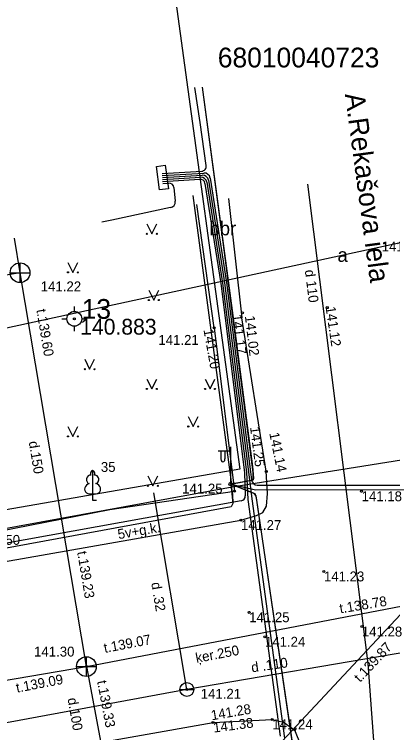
# Model space of a CAD drawing. Extents: x 728492 to 729038, y 272968 to 273171.
# Drawn here: x 728801.6 to 728820.75, y 273094.51 to 273130.85 of the extents above; entities that cross this region are included whole.
import ezdxf

# ---------------------------------------------------------------- set-up
doc = ezdxf.new("R2010")
doc.units = 0
for name, color, linetype in [('APGR_SARK_####_####_#', 7, 'Continuous'), ('APGS_ACRL_####_####_#', 7, 'Continuous'), ('APGS_ELEM_####_####_#', 7, 'Continuous'), ('APGS_VADP_ZSPR_####_I', 7, 'Continuous'), ('CELI_CAPM_####_####_#', 7, 'Continuous'), ('CELI_CMAL_####_####_#', 7, 'Continuous'), ('CELI_CSEG_####_TKST_#', 7, 'Continuous'), ('CELI_IELA_####_TKST_#', 7, 'Continuous'), ('ELEK_ELEM_####_####_#', 7, 'Continuous'), ('ELEK_VADP_ZSPR_####_I', 7, 'Continuous'), ('ELEK_VADV_ZSPR_TKST_#', 7, 'Continuous'), ('GEOD_ELEM_####_####_#', 7, 'Continuous'), ('GEOD_ELEM_####_TKST_#', 7, 'Continuous'), ('RAMI_UZMR_####_####_#', 7, 'Continuous'), ('RELJ_AATZ_####_TKST_#', 7, 'Continuous'), ('RELJ_ELEM_####_####_#', 7, 'Continuous'), ('ROBZ_KADS_####_TKST_#', 7, 'Continuous'), ('ROBZ_UZMR_####_####_#', 7, 'Continuous'), ('SKAN_ELEM_####_####_#', 7, 'Continuous'), ('SKAN_ELEM_PAST_TKST_#', 7, 'Continuous'), ('SKAN_VADP_PAST_####_#', 7, 'Continuous'), ('SKAN_VADP_PAST_TKST_#', 7, 'Continuous'), ('TERT_DIAM_####_TKST_#', 7, 'Continuous'), ('TERT_ELEM_####_####_#', 7, 'Continuous'), ('UDTK_ELEM_####_####_#', 7, 'Continuous'), ('UDTK_ELEM_####_TKST_#', 7, 'Continuous'), ('UDTK_VADP_UDEN_####_#', 7, 'Continuous'), ('UDTK_VADP_UDEN_TKST_#', 7, 'Continuous')]:
    doc.layers.add(name, color=color, linetype=linetype)

msp = doc.modelspace()

# ---------------------------------------------------------------- linework, layer by layer
at = {"layer": 'APGR_SARK_####_####_#'}
for points in [[(728809.481, 273133.58), (728813.011, 273107.831)], [(728813.011, 273107.831), (728678.847, 273084.513)]]:
    msp.add_lwpolyline(points, dxfattribs=at)
at = {"layer": 'APGS_ACRL_####_####_#'}
for points in [[(728812.551, 273107.084), (728813.681, 273107.292), (728813.683, 273107.676), (728812.175, 273119.32), (728811.115, 273127.168)], [(728812.551, 273107.084), (728813.808, 273106.798), (728827.684, 273106.812), (728831.005, 273108.951), (728844.549, 273111.459)], [(728812.551, 273107.084), (728812.657, 273106.097), (728812.582, 273105.93), (728789.256, 273101.647)], [(728819.245, 273070.039), (728816.435, 273088.774), (728813.852, 273106.392), (728813.783, 273106.59), (728812.551, 273107.084)]]:
    msp.add_lwpolyline(points, dxfattribs=at)
at = {"layer": 'APGS_ELEM_####_####_#'}
for p, q in [((728812.551, 273108.751), (728811.916, 273108.746)), ((728812.051, 273108.747), (728812.051, 273108.355)), ((728812.261, 273108.749), (728812.261, 273108.355)), ((728812.551, 273107.084), (728812.551, 273108.967))]:
    msp.add_line(p, q, dxfattribs=at)
msp.add_circle((728812.551, 273107.084), 0.09, dxfattribs=at)
msp.add_ellipse((728812.156, 273108.355), major_axis=(0, 0.151), ratio=0.695971, start_param=1.570796, end_param=4.712389, dxfattribs=at)
at = {"layer": 'APGS_VADP_ZSPR_####_I'}
for points in [[(728811.109, 273127.168), (728812.666, 273115.604), (728813.66, 273107.967), (728813.707, 273107.385), (728813.681, 273107.292), (728813.602, 273107.257), (728812.551, 273107.084)], [(728812.551, 273107.084), (728813.18, 273106.941), (728813.808, 273106.798), (728827.684, 273106.812), (728831.005, 273108.951), (728843.77, 273111.313)], [(728812.551, 273107.084), (728812.644, 273106.556), (728812.657, 273106.097), (728812.582, 273105.93), (728789.256, 273101.647)], [(728812.551, 273107.084), (728813.167, 273106.837), (728813.712, 273106.629), (728813.818, 273106.491), (728816.417, 273088.868), (728819.242, 273070.038)]]:
    msp.add_lwpolyline(points, dxfattribs=at)
at = {"layer": 'CELI_CAPM_####_####_#'}
msp.add_line((728814.353, 273107.731), (728813.116, 273115.489), dxfattribs=at)
for points in [[(728812.431, 273121.524), (728813.116, 273115.489)], [(728778, 273098.805), (728793.44, 273101.816), (728813.067, 273105.258), (728813.855, 273105.497), (728814.183, 273105.647), (728814.358, 273105.969), (728814.419, 273106.601), (728814.353, 273107.731)], [(728676.374, 273071.049), (728680.397, 273071.606), (728696.384, 273074.602), (728721.076, 273079.042), (728739.743, 273082.405), (728759.114, 273085.751), (728811.654, 273095.023), (728814.654, 273095.178), (728815.22, 273095.032), (728815.785, 273094.657), (728816.384, 273093.154), (728816.384, 273093.154), (728817.477, 273084.163), (728819.159, 273072.476)]]:
    msp.add_lwpolyline(points, dxfattribs=at)
at = {"layer": 'CELI_CMAL_####_####_#'}
for p, q in [((728811.715, 273114.983), (728810.832, 273121.229)), ((728811.715, 273114.983), (728812.742, 273106.717)), ((728806.433, 273105.789), (728812.742, 273106.717)), ((728799.84, 273104.509), (728806.433, 273105.789))]:
    msp.add_line(p, q, dxfattribs=at)
at = {"layer": 'ELEK_ELEM_####_####_#'}
msp.add_lwpolyline([(728809.235, 273123.213), (728809.395, 273122.023), (728808.949, 273121.963), (728808.789, 273123.153)], close=True, dxfattribs=at)
at = {"layer": 'ELEK_VADP_ZSPR_####_I'}
for p, q in [((728809.08, 273122.788), (728811.081, 273122.912)), ((728809.086, 273122.688), (728811.193, 273122.819)), ((728809.098, 273122.488), (728811.024, 273122.608)), ((728809.104, 273122.388), (728810.985, 273122.505)), ((728809.111, 273122.289), (728809.412, 273122.307)), ((728813.896, 273107.029), (728827.6, 273107.031))]:
    msp.add_line(p, q, dxfattribs=at)
for points in [[(728811.313, 273123.197), (728810.998, 273125.369), (728810.741, 273127.145)], [(728809.092, 273122.588), (728811.109, 273122.713)], [(728811.423, 273122.46), (728812.242, 273117.263), (728813.45, 273107.695), (728813.612, 273106.329)], [(728811.508, 273122.566), (728812.341, 273117.277), (728813.549, 273107.707), (728813.598, 273107.294)], [(728809.677, 273122.081), (728809.743, 273121.389)], [(728811.247, 273122.294), (728812.044, 273117.235), (728813.251, 273107.671), (728813.291, 273106.493)], [(728811.339, 273122.355), (728812.143, 273117.249), (728813.351, 273107.683), (728813.414, 273106.302)], [(728809.506, 273121.068), (728806.535, 273120.438), (728806.027, 273120.336)], [(728813.085, 273106.238), (728796.045, 273103.161), (728789.187, 273101.908)], [(728813.414, 273106.302), (728815.05, 273094.332)], [(728813.612, 273106.329), (728815.267, 273094.223)], [(728814.95, 273095.437), (728814.949, 273095.442)]]:
    msp.add_lwpolyline(points, dxfattribs=at)
for centre, radius, start, end in [((728811.066, 273123.161), 0.25, 273.5498, 8.2577), ((728811.212, 273122.519), 0.3, 8.95, 93.5498), ((728811, 273122.256), 0.25, 8.95, 93.5498), ((728811.042, 273122.308), 0.3, 8.95, 93.5498), ((728811.127, 273122.414), 0.3, 8.95, 93.5498), ((728809.428, 273122.058), 0.25, 5.4443, 93.5498), ((728809.444, 273121.361), 0.3, 281.9628, 5.4443), ((728813.896, 273107.329), 0.3, 186.7703, 270.0082), ((728813.041, 273106.484), 0.25, 280.2364, 1.911)]:
    msp.add_arc(centre, radius, start, end, dxfattribs=at)
at = {"layer": 'GEOD_ELEM_####_####_#'}
for p, q in [((728804.633, 273115.818), (728804.633, 273116.068)), ((728804.008, 273115.443), (728804.258, 273115.443)), ((728805.008, 273115.443), (728805.258, 273115.443)), ((728804.633, 273114.818), (728804.633, 273115.068))]:
    msp.add_line(p, q, dxfattribs=at)
for radius in [0.375, 0.05]:
    msp.add_circle((728804.633, 273115.443), radius, dxfattribs=at)
at = {"layer": 'RAMI_UZMR_####_####_#'}
msp.add_lwpolyline([(728688.721, 273058.407), (728702.149, 273066.922), (728733.452, 273072.937), (728813.127, 273088.247), (728815.181, 273072.879), (728831.342, 273076.994), (728831.817, 273091.35), (728930.137, 273106.573), (728962.389, 273111.567), (728966.363, 273103.835), (728988.796, 273109.153), (728985.811, 273141.417), (728955.146, 273144.603), (728957.616, 273137.975), (728904.333, 273130.641), (728847.677, 273120.095), (728823.483, 273119.793), (728790.036, 273112.558), (728726.814, 273102.175), (728686.914, 273096.216)], dxfattribs=at)
at = {"layer": 'RELJ_ELEM_####_####_#'}
for centre in [(728817.442, 273116.008), (728813.143, 273115.752), (728811.715, 273114.983), (728814.353, 273107.722), (728812.742, 273106.717), (728819.178, 273106.716), (728813.067, 273105.258), (728817.27, 273102.659), (728813.485, 273100.593), (728819.19, 273099.871), (728814.283, 273099.354), (728805.243, 273097.85), (728810.333, 273096.686), (728814.654, 273095.178), (728811.654, 273095.023), (728815.785, 273094.657)]:
    msp.add_circle(centre, 0.05, dxfattribs=at)
at = {"layer": 'ROBZ_UZMR_####_####_#'}
for p, q in [((728812.63, 273106.926), (728810.654, 273121.683)), ((728824.732, 273108.848), (728812.63, 273106.926)), ((728812.63, 273106.926), (728799.992, 273104.613))]:
    msp.add_line(p, q, dxfattribs=at)
at = {"layer": 'SKAN_ELEM_####_####_#'}
for p, q in [((728801.886, 273117.277), (728801.886, 273118.277)), ((728801.386, 273117.777), (728802.386, 273117.777)), ((728805.243, 273097.35), (728805.243, 273098.35)), ((728804.743, 273097.85), (728805.743, 273097.85))]:
    msp.add_line(p, q, dxfattribs=at)
for centre in [(728801.886, 273117.777), (728805.243, 273097.85)]:
    msp.add_circle(centre, 0.5, dxfattribs=at)
at = {"layer": 'SKAN_VADP_PAST_####_#'}
for points in [[(728801.886, 273117.777), (728801.604, 273119.526)], [(728805.243, 273097.85), (728801.886, 273117.777), (728797.924, 273117.11)], [(728805.243, 273097.85), (728821.624, 273100.995), (728813.478, 273092.29)], [(728754.421, 273088.922), (728770.492, 273091.941), (728805.243, 273097.85), (728806.524, 273091.029)]]:
    msp.add_lwpolyline(points, dxfattribs=at)
at = {"layer": 'TERT_ELEM_####_####_#'}
for p, q in [((728808.306, 273120.244), (728808.556, 273119.744)), ((728808.556, 273119.744), (728808.806, 273120.244)), ((728804.31, 273118.294), (728804.56, 273117.794)), ((728804.56, 273117.794), (728804.81, 273118.294)), ((728808.406, 273116.894), (728808.656, 273116.394)), ((728808.656, 273116.394), (728808.906, 273116.894)), ((728805.159, 273113.394), (728805.409, 273112.894)), ((728805.409, 273112.894), (728805.659, 273113.394)), ((728808.306, 273112.394), (728808.556, 273111.894)), ((728808.556, 273111.894), (728808.806, 273112.394)), ((728811.253, 273112.394), (728811.503, 273111.894)), ((728811.503, 273111.894), (728811.753, 273112.394)), ((728810.404, 273110.494), (728810.654, 273109.994)), ((728810.654, 273109.994), (728810.904, 273110.494)), ((728804.31, 273109.994), (728804.56, 273109.494)), ((728804.56, 273109.494), (728804.81, 273109.994)), ((728808.356, 273107.495), (728808.606, 273106.995)), ((728808.606, 273106.995), (728808.856, 273107.495)), ((728805.559, 273106.611), (728805.559, 273106.264)), ((728805.559, 273106.264), (728805.759, 273106.264))]:
    msp.add_line(p, q, dxfattribs=at)
for points in [[(728805.559, 273107.764), (728805.559, 273106.611)], [(728805.649, 273107.532), (728805.648, 273107.533)]]:
    msp.add_lwpolyline(points, dxfattribs=at)
for centre, radius in [((728808.306, 273119.743), 0.028), ((728808.806, 273119.743), 0.0263), ((728804.31, 273117.793), 0.028), ((728804.81, 273117.793), 0.0263), ((728808.406, 273116.394), 0.028), ((728808.906, 273116.394), 0.0263), ((728805.159, 273112.894), 0.028), ((728805.659, 273112.894), 0.0263), ((728808.306, 273111.894), 0.028), ((728808.806, 273111.894), 0.0263), ((728811.253, 273111.894), 0.028), ((728811.753, 273111.894), 0.0263), ((728810.403, 273109.994), 0.028), ((728810.903, 273109.994), 0.0263), ((728804.31, 273109.494), 0.028), ((728804.81, 273109.494), 0.0263), ((728808.356, 273106.994), 0.028), ((728808.856, 273106.994), 0.0263)]:
    msp.add_circle(centre, radius, dxfattribs=at)
for centre, major_axis, ratio, start_param, end_param in [((728805.431, 273107.319), (-0.039, -0.212), 0.861323, 3.141593, 6.283185), ((728805.559, 273107.614), (0, -0.15), 0.707107, 3.14537, 5.287485), ((728805.559, 273107.614), (0, -0.15), 0.707107, 0.995701, 3.137816), ((728805.687, 273107.319), (0.039, -0.212), 0.861323, 0, 3.141593), ((728805.469, 273106.857), (0.307, 0.095), 0.814445, 1.570796, 4.752015), ((728805.649, 273106.857), (-0.307, 0.095), 0.814445, 1.531171, 4.712389)]:
    msp.add_ellipse(centre, major_axis=major_axis, ratio=ratio, start_param=start_param, end_param=end_param, dxfattribs=at)
at = {"layer": 'UDTK_ELEM_####_####_#'}
for p, q in [((728809.982, 273096.686), (728810.684, 273096.686)), ((728810.332, 273096.686), (728810.332, 273096.687))]:
    msp.add_line(p, q, dxfattribs=at)
msp.add_circle((728810.333, 273096.686), 0.351, dxfattribs=at)
at = {"layer": 'UDTK_VADP_UDEN_####_#'}
for p, q in [((728810.333, 273096.686), (728808.658, 273106.631)), ((728848.448, 273103.204), (728810.333, 273096.686)), ((728810.333, 273096.686), (728792.824, 273093.45))]:
    msp.add_line(p, q, dxfattribs=at)
for points in [[(728816.436, 273122.263), (728819.492, 273098.009)], [(728819.492, 273098.009), (728820.62, 273082.615)]]:
    msp.add_lwpolyline(points, dxfattribs=at)

# ---------------------------------------------------------------- texts
at = {"layer": 'CELI_CSEG_####_TKST_#'}
for s, p in [('bbr', (728811.476, 273119.667)), ('a', (728817.959, 273118.324))]:
    msp.add_text(s, height=0.7, dxfattribs=at).set_placement(p)
at = {"layer": 'CELI_IELA_####_TKST_#'}
msp.add_text('A.Rekašova iela', height=1, rotation=277.641, dxfattribs=at).set_placement((728818.33, 273126.807))
at = {"layer": 'ELEK_VADV_ZSPR_TKST_#'}
msp.add_text('5v+g.k.', height=0.5, rotation=9.797, dxfattribs=at).set_placement((728806.873, 273104.292))
at = {"layer": 'GEOD_ELEM_####_TKST_#'}
for s, height, p in [(' 13', 1, (728804.633, 273115.443)), (' 140.883', 0.8, (728804.633, 273114.643))]:
    msp.add_text(s, height=height, dxfattribs=at).set_placement(p)
at = {"layer": 'RELJ_AATZ_####_TKST_#'}
for s, p in [(' 141.16', (728820.014, 273118.854)), (' 141.21', (728808.704, 273114.126)), ('141.25', (728810.092, 273106.605)), ('141.18', (728819.178, 273106.216)), ('141.27', (728813.067, 273104.758)), ('141.50', (728799.84, 273104.009)), ('141.23', (728817.27, 273102.159)), ('141.25', (728813.485, 273100.093)), ('141.28', (728819.19, 273099.371)), ('141.24', (728814.283, 273098.854)), ('141.24', (728814.654, 273094.678))]:
    msp.add_text(s, height=0.5, dxfattribs=at).set_placement(p)
for s, rotation, p in [('141.12', 278.4301, (728817.352, 273116.034)), ('141.17', 277.1192, (728812.612, 273115.645)), ('141.02', 276.7044, (728813.267, 273115.578)), ('141.20', 280.2139, (728811.169, 273114.884)), ('141.25', 277.3584, (728813.527, 273109.959)), ('141.14', 281.5231, (728814.499, 273109.654)), ('141.28', 9.7746, (728811.597, 273095.129)), ('141.38', 7.413, (728811.697, 273094.508))]:
    msp.add_text(s, height=0.5, rotation=rotation, dxfattribs=at).set_placement(p)
at = {"layer": 'ROBZ_KADS_####_TKST_#'}
msp.add_text('68010040723', height=1, dxfattribs=at).set_placement((728811.896, 273128.162))
at = {"layer": 'SKAN_ELEM_####_####_#'}
msp.add_text('141.30', height=0.5, dxfattribs=at).set_placement((728802.593, 273098.357))
at = {"layer": 'SKAN_ELEM_PAST_TKST_#'}
msp.add_text(' 141.22', height=0.5, dxfattribs=at).set_placement((728802.747, 273116.832))
at = {"layer": 'SKAN_VADP_PAST_TKST_#'}
for s, rotation, p in [('t.139.60', 279.563, (728802.709, 273115.896)), ('d.150', 279.563, (728802.32, 273109.217)), ('t.139.23', 279.563, (728804.773, 273103.645)), ('t.138.78', 9.383, (728818.101, 273100.536)), ('t.139.07', 10.868, (728806.173, 273098.537)), ('ķer.250', 10.868, (728810.821, 273098.031)), ('t.139.87', 46.899, (728819.102, 273097.026)), ('t.139.09', 10.868, (728801.729, 273096.526)), ('t.139.33', 280.638, (728805.782, 273097.104)), ('d.100', 279.936, (728804.288, 273096.227))]:
    msp.add_text(s, height=0.5, rotation=rotation, dxfattribs=at).set_placement(p)
at = {"layer": 'TERT_DIAM_####_TKST_#'}
msp.add_text('35', height=0.5, dxfattribs=at).set_placement((728805.976, 273107.699))
at = {"layer": 'UDTK_ELEM_####_TKST_#'}
msp.add_text('141.21', height=0.5, dxfattribs=at).set_placement((728811.033, 273096.223))
at = {"layer": 'UDTK_VADP_UDEN_TKST_#'}
for s, rotation, p in [('d 110', 277.1825, (728816.302, 273117.898)), ('d .32', 279.5604, (728808.521, 273102.076)), ('d .110', 8.2194, (728813.628, 273097.552))]:
    msp.add_text(s, height=0.5, rotation=rotation, dxfattribs=at).set_placement(p)

doc.saveas('drawing.dxf')
